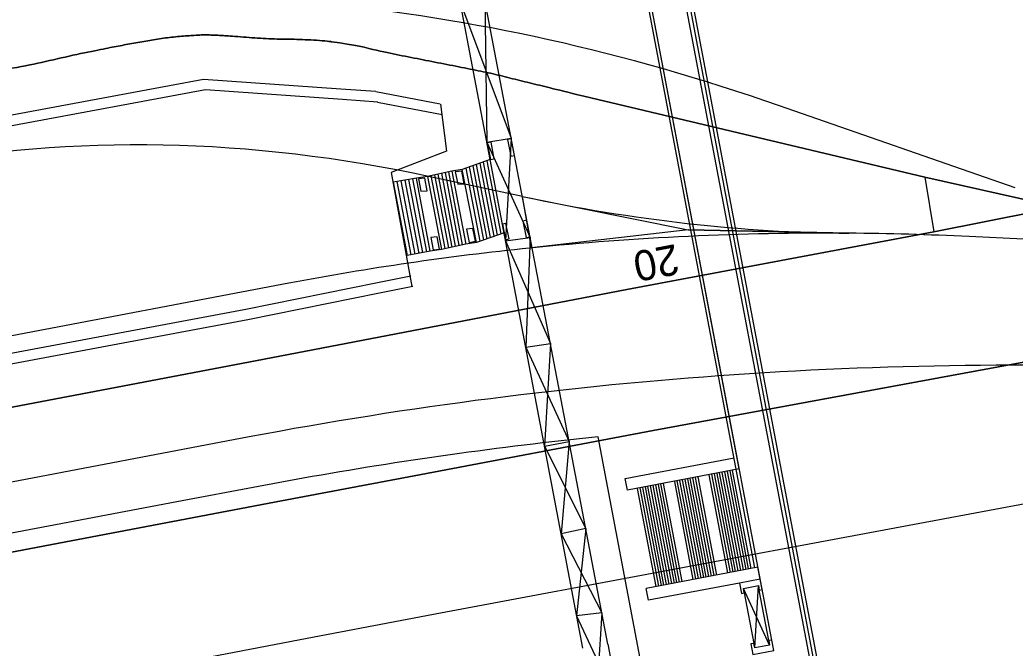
# Model space of a CAD drawing. Extents: x 6541740 to 6566395, y 5525066 to 5530361.
# Drawn here: x 6564300.3 to 6564333.2, y 5527856.49 to 5527877.26 of the extents above; entities that cross this region are included whole.
import ezdxf

# ---------------------------------------------------------------- set-up
doc = ezdxf.new("R2010")
doc.units = 0
for name, color, linetype in [('TOR_PRZEK_P-pomoc', 7, 'Continuous'), ('TOR_PS_OPIS_O-opisy odwodnienia', 7, 'Continuous'), ('TOR_PS_T-rowy otwarte nieumocnione', 7, 'Continuous'), ('TOR_PS_T-rowy otwarte umocnione', 7, 'Continuous'), ('TOR_PS_T-rozjazdy projektowane', 7, 'Continuous'), ('TOR_PS_T-umocnienia skarp', 7, 'Continuous'), ('TOR_W-warstwa dodatkowa 2', 7, 'Continuous')]:
    doc.layers.add(name, color=color, linetype=linetype)

msp = doc.modelspace()

# ---------------------------------------------------------------- linework, layer by layer
at = {"layer": 'TOR_PRZEK_P-pomoc'}
for p, q in [((6564321.122, 5527854.471), (6564319.415, 5527863.477)), ((6564309.66, 5527862.106), (6564308.186, 5527861.838)), ((6564308.186, 5527861.838), (6564305.483, 5527861.328)), ((6564305.483, 5527861.328), (6564270.2, 5527854.64))]:
    msp.add_line(p, q, dxfattribs=at)
msp.add_ellipse((6564708.282, 5525751.101), major_axis=(-400.096, 2110.735), ratio=0.25, start_param=6.262073, end_param=6.280395, dxfattribs=at)
at = {"layer": 'TOR_PS_T-rowy otwarte nieumocnione'}
for p, q in [((6564339.002, 5527870.069), (6564330.218, 5527872.062)), ((6564330.218, 5527872.062), (6564339.002, 5527870.069)), ((6564334.609, 5527871.066), (6564330.506, 5527870.249)), ((6564330.506, 5527870.249), (6564334.609, 5527871.066))]:
    msp.add_line(p, q, dxfattribs=at)
for points in [[(6564319.167, 5527874.679), (6564330.218, 5527872.062)], [(6564330.218, 5527872.062), (6564319.167, 5527874.679)], [(6564312.45, 5527866.828), (6564320.362, 5527868.344), (6564330.506, 5527870.249)], [(6564330.506, 5527870.249), (6564320.362, 5527868.344), (6564312.45, 5527866.828)], [(6564282.69, 5527861.179), (6564295.682, 5527863.632), (6564308.08, 5527865.992), (6564312.45, 5527866.828)], [(6564312.45, 5527866.828), (6564308.08, 5527865.992), (6564295.682, 5527863.632), (6564282.69, 5527861.179)], [(6564333.49, 5527865.946), (6564321.23, 5527863.682), (6564313.333, 5527862.186)], [(6564313.333, 5527862.186), (6564321.23, 5527863.682), (6564333.49, 5527865.946)], [(6564313.333, 5527862.186), (6564308.947, 5527861.355), (6564296.589, 5527859.016), (6564283.561, 5527856.55)], [(6564283.561, 5527856.55), (6564296.589, 5527859.016), (6564308.947, 5527861.355), (6564313.333, 5527862.186)], [(6564334.355, 5527861.413), (6564322.078, 5527859.121), (6564314.197, 5527857.643)], [(6564314.197, 5527857.644), (6564309.79, 5527856.811), (6564297.479, 5527854.451), (6564284.434, 5527851.98)]]:
    msp.add_lwpolyline(points, dxfattribs=at)
for points in [[(6564315.976, 5527872.664), (6564315.871, 5527873.217), (6564315.746, 5527873.191), (6564315.852, 5527872.644)], [(6564316.646, 5527872.774), (6564316.54, 5527873.326), (6564316.416, 5527873.3), (6564316.521, 5527872.753)], [(6564314.905, 5527872.258), (6564314.691, 5527872.234), (6564314.769, 5527871.826), (6564314.983, 5527871.841)], [(6564314.905, 5527872.258), (6564314.691, 5527872.234), (6564314.769, 5527871.826), (6564314.983, 5527871.841)], [(6564313.686, 5527872.029), (6564313.473, 5527872.004), (6564313.551, 5527871.597), (6564313.765, 5527871.612)], [(6564313.686, 5527872.029), (6564313.473, 5527872.004), (6564313.551, 5527871.597), (6564313.765, 5527871.612)], [(6564334.609, 5527871.066), (6564330.218, 5527872.062), (6564330.506, 5527870.249)], [(6564316.468, 5527870.022), (6564316.365, 5527870.523), (6564316.25, 5527870.502), (6564316.351, 5527869.987)], [(6564317.156, 5527870.083), (6564317.05, 5527870.635), (6564316.926, 5527870.609), (6564317.031, 5527870.062)], [(6564315.275, 5527870.363), (6564315.062, 5527870.338), (6564315.144, 5527869.898), (6564315.354, 5527869.946)], [(6564314.089, 5527870.084), (6564313.876, 5527870.059), (6564313.953, 5527869.652), (6564314.166, 5527869.681)]]:
    msp.add_lwpolyline(points, close=True, dxfattribs=at)
for points in [[(6564293.582, 5527874.503), (6564295.669, 5527874.877), (6564297.756, 5527875.251), (6564299.843, 5527875.625), (6564300.887, 5527875.812), (6564301.918, 5527876.065), (6564302.957, 5527876.275), (6564303.477, 5527876.38), (6564303.998, 5527876.476), (6564304.521, 5527876.567), (6564305.043, 5527876.658), (6564305.571, 5527876.713), (6564306.104, 5527876.747), (6564306.287, 5527876.759), (6564306.47, 5527876.763), (6564306.656, 5527876.755), (6564306.842, 5527876.748), (6564307.029, 5527876.738), (6564307.215, 5527876.725), (6564307.589, 5527876.701), (6564307.965, 5527876.664), (6564308.338, 5527876.642), (6564308.711, 5527876.621), (6564309.079, 5527876.628), (6564309.451, 5527876.612), (6564309.823, 5527876.595), (6564310.195, 5527876.584), (6564310.572, 5527876.538), (6564310.583, 5527876.536), (6564310.594, 5527876.535), (6564310.605, 5527876.534)], [(6564310.605, 5527876.534), (6564310.594, 5527876.535), (6564310.583, 5527876.536), (6564310.572, 5527876.538), (6564310.195, 5527876.584), (6564309.823, 5527876.595), (6564309.451, 5527876.612), (6564309.079, 5527876.628), (6564308.711, 5527876.621), (6564308.338, 5527876.642), (6564307.965, 5527876.664), (6564307.589, 5527876.701), (6564307.215, 5527876.725), (6564307.029, 5527876.738), (6564306.842, 5527876.748), (6564306.656, 5527876.755), (6564306.47, 5527876.763), (6564306.287, 5527876.759), (6564306.104, 5527876.747), (6564305.571, 5527876.713), (6564305.043, 5527876.658), (6564304.521, 5527876.567), (6564303.998, 5527876.476), (6564303.477, 5527876.38), (6564302.957, 5527876.275), (6564301.918, 5527876.065), (6564300.887, 5527875.812), (6564299.843, 5527875.625), (6564297.756, 5527875.251), (6564295.669, 5527874.877), (6564293.582, 5527874.503)], [(6564310.605, 5527876.534), (6564311.372, 5527876.436), (6564312.157, 5527876.226), (6564312.934, 5527876.073), (6564313.721, 5527875.918), (6564314.508, 5527875.766), (6564315.295, 5527875.608), (6564315.936, 5527875.48), (6564316.584, 5527875.312), (6564317.229, 5527875.154), (6564317.875, 5527874.997), (6564318.521, 5527874.834), (6564319.167, 5527874.679)], [(6564319.167, 5527874.679), (6564318.521, 5527874.834), (6564317.875, 5527874.997), (6564317.229, 5527875.154), (6564316.584, 5527875.312), (6564315.936, 5527875.48), (6564315.295, 5527875.608), (6564314.508, 5527875.766), (6564313.721, 5527875.918), (6564312.934, 5527876.073), (6564312.157, 5527876.226), (6564311.372, 5527876.436), (6564310.605, 5527876.534)]]:
    msp.add_open_spline(points, degree=3, dxfattribs=at)
at = {"layer": 'TOR_PS_T-rowy otwarte umocnione'}
msp.add_lwpolyline([(6564327.697, 5527870.206), (6564322.391, 5527870.32), (6564317.213, 5527869.719), (6564316.917, 5527871.42), (6564322.391, 5527870.32)], close=True, dxfattribs=at)
at = {"layer": 'TOR_PS_T-rozjazdy projektowane'}
for p, q in [((6564333.198, 5527871.708), (6564325.41, 5527874.418)), ((6564316.916, 5527871.421), (6564313.863, 5527872.074)), ((6564333.475, 5527870.01), (6564331.679, 5527870.095)), ((6564309.189, 5527868.554), (6564250.008, 5527857.336)), ((6564307.876, 5527863.472), (6564253.258, 5527853.119))]:
    msp.add_line(p, q, dxfattribs=at)
for centre, major_axis, start_param, end_param in [((6564445.052, 5527090.139), (-149.176, 786.986), 6.140318, 6.283185), ((6564417.558, 5527233.782), (-121.054, 638.628), 6.178427, 6.283186), ((6564197.198, 5528608.336), (-139.758, 737.304), 3.036834, 3.092261), ((6564588.545, 5526394.797), (-279.355, 1473.757), 6.233856, 6.261759), ((6564588.545, 5526394.797), (-279.355, 1473.757), 6.223462, 6.233856), ((6564588.545, 5526394.797), (-279.355, 1473.757), 6.261759, 6.283188), ((6564708.285, 5525751.086), (-400.409, 2112.386), 6.223138, 6.283185)]:
    msp.add_ellipse(centre, major_axis=major_axis, ratio=0.25, start_param=start_param, end_param=end_param, dxfattribs=at)
at = {"layer": 'TOR_PS_T-umocnienia skarp'}
for p, q in [((6564314.861, 5527877.818), (6564316.541, 5527873.348)), ((6564315.665, 5527877.933), (6564315.734, 5527873.215)), ((6564312.065, 5527874.885), (6564310.905, 5527874.968)), ((6564312.067, 5527874.885), (6564314.195, 5527874.479)), ((6564312.125, 5527874.541), (6564310.965, 5527874.623)), ((6564312.123, 5527874.541), (6564314.252, 5527874.135)), ((6564315.734, 5527873.215), (6564316.541, 5527873.348)), ((6564315.734, 5527873.215), (6564317.167, 5527870.068)), ((6564316.541, 5527873.348), (6564316.351, 5527869.957)), ((6564315.384, 5527872.477), (6564315.848, 5527870.064)), ((6564315.501, 5527872.518), (6564315.964, 5527870.105)), ((6564315.616, 5527872.558), (6564316.079, 5527870.145)), ((6564315.732, 5527872.598), (6564316.194, 5527870.185)), ((6564314.003, 5527872.136), (6564314.46, 5527869.723)), ((6564314.118, 5527872.161), (6564314.575, 5527869.748)), ((6564314.234, 5527872.186), (6564314.691, 5527869.773)), ((6564314.352, 5527872.212), (6564314.806, 5527869.798)), ((6564314.467, 5527872.237), (6564314.921, 5527869.824)), ((6564314.579, 5527872.262), (6564315.036, 5527869.849)), ((6564315.388, 5527869.903), (6564314.922, 5527872.315)), ((6564315.036, 5527872.355), (6564315.502, 5527869.943)), ((6564315.152, 5527872.396), (6564315.618, 5527869.984)), ((6564315.268, 5527872.436), (6564315.733, 5527870.024)), ((6564313.402, 5527872.027), (6564312.633, 5527871.89)), ((6564312.633, 5527871.89), (6564313.096, 5527869.466)), ((6564312.762, 5527871.913), (6564313.224, 5527869.49)), ((6564312.89, 5527871.936), (6564313.352, 5527869.515)), ((6564313.019, 5527871.959), (6564313.48, 5527869.54)), ((6564313.147, 5527871.981), (6564313.608, 5527869.565)), ((6564313.276, 5527872.004), (6564313.736, 5527869.59)), ((6564313.855, 5527869.613), (6564313.402, 5527872.027)), ((6564313.772, 5527872.085), (6564314.229, 5527869.672)), ((6564313.886, 5527872.11), (6564314.345, 5527869.698)), ((6564316.351, 5527869.957), (6564317.167, 5527870.068)), ((6564316.351, 5527869.957), (6564317.836, 5527866.565)), ((6564317.167, 5527870.068), (6564317.018, 5527866.436)), ((6564313.855, 5527869.613), (6564313.096, 5527869.466)), ((6564312.118, 5527868.577), (6564313.222, 5527868.801)), ((6564312.183, 5527868.233), (6564313.288, 5527868.457)), ((6564317.018, 5527866.436), (6564317.836, 5527866.565)), ((6564317.836, 5527866.565), (6564317.637, 5527863.171)), ((6564317.018, 5527866.436), (6564318.456, 5527863.318)), ((6564317.637, 5527863.171), (6564318.456, 5527863.318)), ((6564318.456, 5527863.318), (6564318.188, 5527860.268)), ((6564317.637, 5527863.171), (6564319.005, 5527860.446)), ((6564319.005, 5527860.446), (6564318.188, 5527860.268)), ((6564319.005, 5527860.446), (6564318.701, 5527857.559)), ((6564319.538, 5527857.657), (6564318.701, 5527857.559)), ((6564319.538, 5527857.657), (6564319.322, 5527854.267)), ((6564318.701, 5527857.559), (6564320.144, 5527854.45))]:
    msp.add_line(p, q, dxfattribs=at)
for points in [[(6564319.735, 5527856.626), (6564315.624, 5527878.146), (6564315.08, 5527880.997)], [(6564318.904, 5527856.485), (6564315.843, 5527872.637), (6564314.291, 5527880.829)], [(6564310.905, 5527874.968), (6564306.368, 5527875.29), (6564293.862, 5527872.965), (6564280.878, 5527870.536)], [(6564310.965, 5527874.623), (6564306.43, 5527874.946), (6564293.928, 5527872.621), (6564280.943, 5527870.192)], [(6564314.202, 5527874.474), (6564314.402, 5527872.914), (6564312.571, 5527872.218), (6564313.258, 5527868.448)], [(6564315.843, 5527872.637), (6564314.922, 5527872.315), (6564314.579, 5527872.262), (6564313.772, 5527872.085), (6564313.402, 5527872.027)], [(6564316.301, 5527870.223), (6564315.388, 5527869.903), (6564315.036, 5527869.849), (6564314.229, 5527869.672), (6564313.855, 5527869.613)], [(6564282.386, 5527862.876), (6564295.34, 5527865.373), (6564307.765, 5527867.693), (6564312.118, 5527868.577)], [(6564282.451, 5527862.532), (6564295.405, 5527865.029), (6564307.83, 5527867.349), (6564312.183, 5527868.233)], [(6564318.188, 5527860.268), (6564319.538, 5527857.657)], [(6564319.735, 5527856.626), (6564320.873, 5527850.582), (6564321.301, 5527848.307), (6564330.786, 5527797.936)]]:
    msp.add_lwpolyline(points, dxfattribs=at)
for points in [[(6564315.976, 5527872.664), (6564315.871, 5527873.217), (6564315.746, 5527873.191), (6564315.852, 5527872.644)], [(6564316.646, 5527872.774), (6564316.54, 5527873.326), (6564316.416, 5527873.3), (6564316.521, 5527872.753)], [(6564316.468, 5527870.022), (6564316.365, 5527870.523), (6564316.25, 5527870.502), (6564316.351, 5527869.987)], [(6564317.156, 5527870.083), (6564317.05, 5527870.635), (6564316.926, 5527870.609), (6564317.031, 5527870.062)], [(6564315.275, 5527870.363), (6564315.062, 5527870.338), (6564315.144, 5527869.898), (6564315.354, 5527869.946)], [(6564314.089, 5527870.084), (6564313.876, 5527870.059), (6564313.953, 5527869.652), (6564314.166, 5527869.681)]]:
    msp.add_lwpolyline(points, close=True, dxfattribs=at)
at = {"layer": 'TOR_W-warstwa dodatkowa 2'}
for p, q in [((6564332.533, 5527824.527), (6564321.254, 5527884.03)), ((6564321.353, 5527884.048), (6564332.706, 5527824.152)), ((6564325.151, 5527856.759), (6564320.026, 5527883.797)), ((6564324.078, 5527862.419), (6564320.026, 5527883.797)), ((6564333.174, 5527820.475), (6564321.178, 5527883.761)), ((6564324.597, 5527859.147), (6564320.002, 5527883.385)), ((6564320.309, 5527862.1), (6564323.908, 5527862.782)), ((6564320.309, 5527862.1), (6564323.908, 5527862.782)), ((6564324.078, 5527862.419), (6564320.384, 5527861.707)), ((6564324.078, 5527862.419), (6564320.384, 5527861.707)), ((6564323.872, 5527859.01), (6564323.258, 5527862.252)), ((6564323.958, 5527859.026), (6564323.344, 5527862.268)), ((6564324.044, 5527859.042), (6564323.43, 5527862.285)), ((6564324.13, 5527859.059), (6564323.516, 5527862.301)), ((6564324.216, 5527859.075), (6564323.601, 5527862.317)), ((6564324.302, 5527859.091), (6564323.687, 5527862.334)), ((6564324.388, 5527859.108), (6564323.773, 5527862.35)), ((6564324.474, 5527859.124), (6564323.859, 5527862.366)), ((6564320.384, 5527861.707), (6564320.309, 5527862.1)), ((6564320.384, 5527861.707), (6564320.309, 5527862.1)), ((6564322.104, 5527858.675), (6564321.489, 5527861.917)), ((6564322.19, 5527858.691), (6564321.575, 5527861.933)), ((6564322.558, 5527858.761), (6564321.943, 5527862.003)), ((6564322.644, 5527858.777), (6564322.029, 5527862.019)), ((6564322.73, 5527858.793), (6564322.115, 5527862.036)), ((6564322.816, 5527858.81), (6564322.201, 5527862.052)), ((6564322.902, 5527858.826), (6564322.287, 5527862.068)), ((6564322.988, 5527858.842), (6564322.373, 5527862.085)), ((6564323.074, 5527858.859), (6564322.459, 5527862.101)), ((6564323.16, 5527858.875), (6564322.545, 5527862.117)), ((6564323.246, 5527858.891), (6564322.631, 5527862.133)), ((6564323.332, 5527858.907), (6564322.717, 5527862.15)), ((6564323.7, 5527858.977), (6564323.086, 5527862.22)), ((6564323.786, 5527858.994), (6564323.172, 5527862.236)), ((6564321.33, 5527858.528), (6564320.715, 5527861.77)), ((6564321.416, 5527858.544), (6564320.801, 5527861.787)), ((6564321.502, 5527858.561), (6564320.887, 5527861.803)), ((6564321.588, 5527858.577), (6564320.973, 5527861.819)), ((6564321.674, 5527858.593), (6564321.059, 5527861.835)), ((6564321.76, 5527858.609), (6564321.145, 5527861.852)), ((6564321.846, 5527858.626), (6564321.231, 5527861.868)), ((6564321.932, 5527858.642), (6564321.317, 5527861.884)), ((6564322.018, 5527858.658), (6564321.403, 5527861.901)), ((6564325.081, 5527856.593), (6564324.217, 5527858.465)), ((6564324.245, 5527858.317), (6564324.562, 5527856.647)), ((6564324.245, 5527858.317), (6564324.562, 5527856.647)), ((6564324.59, 5527856.5), (6564324.709, 5527858.558)), ((6564325.151, 5527856.759), (6564325.053, 5527856.74)), ((6564325.053, 5527856.74), (6564325.081, 5527856.593)), ((6564325.216, 5527856.415), (6564325.151, 5527856.759)), ((6564324.562, 5527856.647), (6564324.464, 5527856.628)), ((6564324.464, 5527856.628), (6564324.529, 5527856.284)), ((6564324.59, 5527856.5), (6564324.562, 5527856.647)), ((6564325.081, 5527856.593), (6564324.59, 5527856.5))]:
    msp.add_line(p, q, dxfattribs=at)
for points in [[(6564324.77, 5527858.773), (6564324.695, 5527859.166), (6564320.998, 5527858.465)], [(6564324.77, 5527858.773), (6564324.695, 5527859.166), (6564320.998, 5527858.465)], [(6564324.082, 5527858.642), (6564321.073, 5527858.072), (6564320.998, 5527858.465)], [(6564324.082, 5527858.642), (6564321.073, 5527858.072), (6564320.998, 5527858.465)], [(6564325.053, 5527856.74), (6564324.736, 5527858.41), (6564324.835, 5527858.429), (6564324.77, 5527858.773), (6564324.082, 5527858.642), (6564324.147, 5527858.299), (6564324.245, 5527858.317), (6564324.217, 5527858.465), (6564324.709, 5527858.558), (6564324.736, 5527858.41)]]:
    msp.add_lwpolyline(points, dxfattribs=at)
msp.add_lwpolyline([(6564325.216, 5527856.415), (6564325.151, 5527856.759), (6564325.053, 5527856.74), (6564325.081, 5527856.593), (6564324.59, 5527856.5), (6564324.562, 5527856.647), (6564324.464, 5527856.628), (6564324.529, 5527856.284)], close=True, dxfattribs=at)

# ---------------------------------------------------------------- texts
at = {"layer": 'TOR_PS_OPIS_O-opisy odwodnienia'}
msp.add_text('20', height=1, rotation=190.7332, dxfattribs=at).set_placement((6564321.974, 5527869.852))

doc.saveas('drawing.dxf')
